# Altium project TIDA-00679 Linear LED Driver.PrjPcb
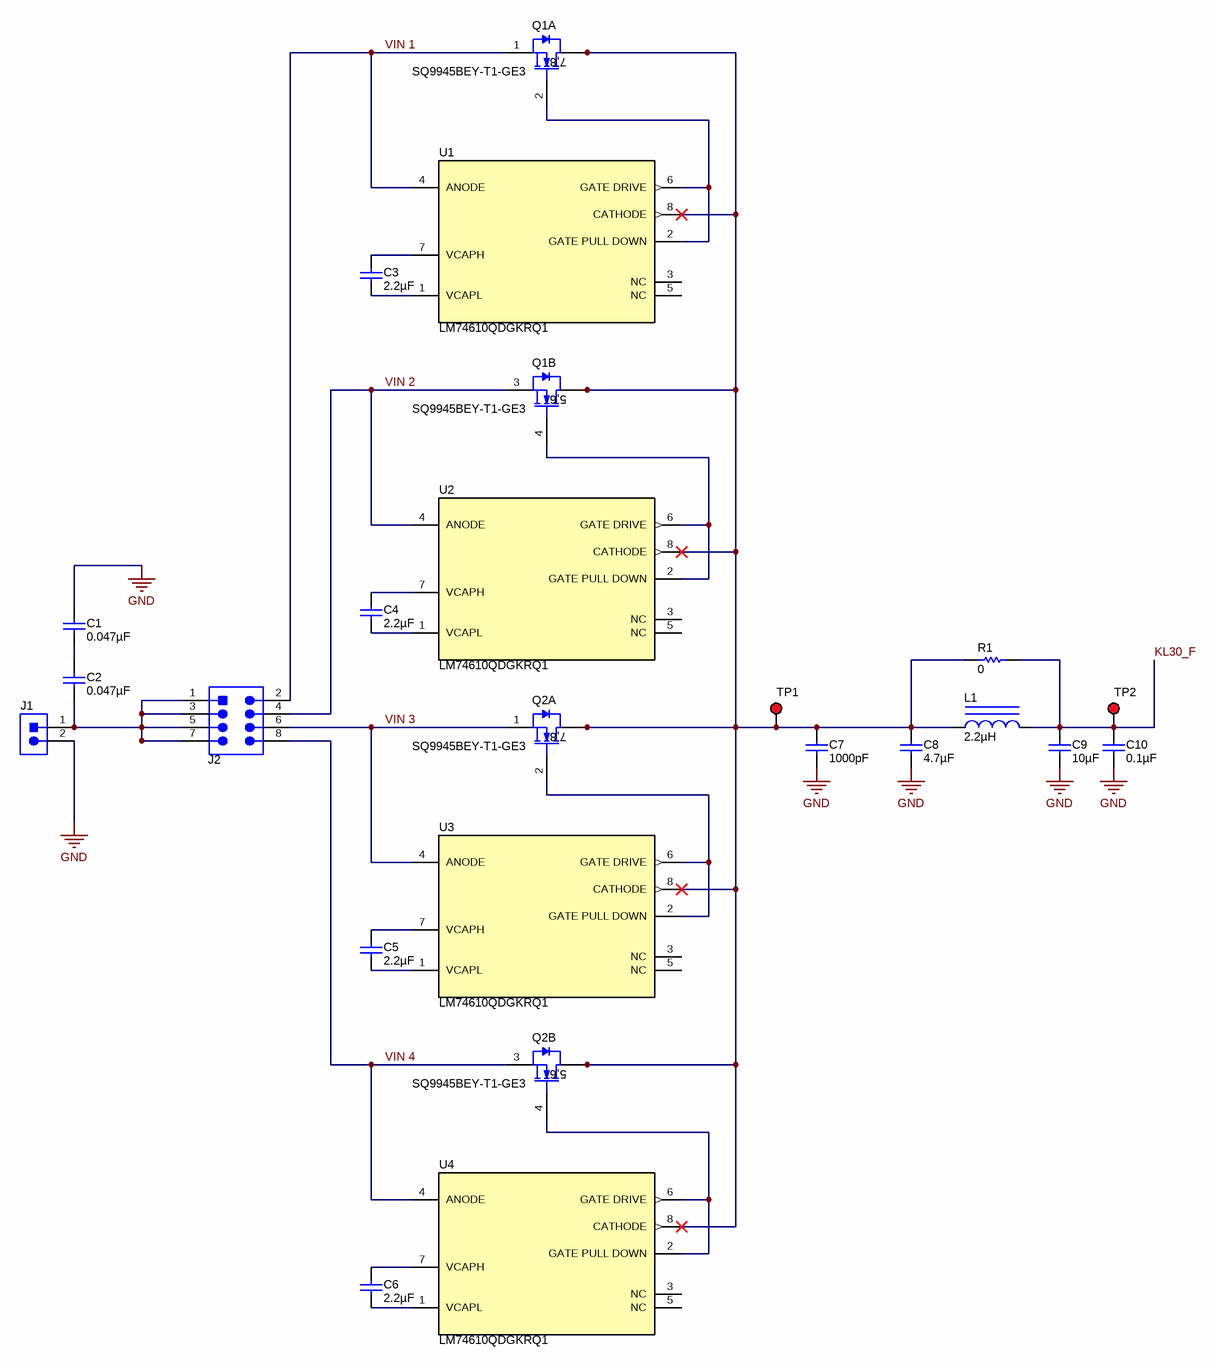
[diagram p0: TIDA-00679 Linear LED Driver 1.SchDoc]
CopyrightYear: 2015; EVM_Orderable: N/A; PCB_Layout: Robert Regensburger; PCB_Rev: E1; PRJ_Customer: Public Release; PRJ_Engineer: Robert Regensburger; PRJ_Number: TIDA-00679; PRJ_Title: Linear LED Driver; SCH_Rev: E1; TechSupport: http://www.ti.com/support; TID: TIDA-00679
3 sheets, 158 parts. Net scope: global (net labels, ports and power ports of the same name join across sheets).
Board file: TIDA-00679 Linear LED Driver.PcbDoc
Sheets:
  TIDA-00679 Linear LED Driver 1.SchDoc
  TIDA-00679 Linear LED Driver 2.SchDoc
  TIDA-00679 Linear LED Driver_Hardware.SchDoc

## Sheet TIDA-00679 Linear LED Driver 1.SchDoc: Linear LED Driver
size 431 x 279 mm; Date: Not shown in title block; ApprovedBy: Not shown in title block; CheckedBy: Not shown in title block; Author: Not shown in title block; CompanyName: Not shown in title block; DrawnBy: Robert Regensburger; Engineer: Not shown in title block; Organization: Not shown in title block; Address1: Not shown in title block; Address2: Not shown in title block; Address3: Not shown in title block; Address4: Not shown in title block; DocumentNumber: 2; Revision: Use project parameter SCH_Rev; SheetNumber: 2; SheetTotal: 4; PageSetup: Record=PageOptions¦CenterHorizontal=True¦CenterVertical=True¦PrintScale=0.62¦XCorrection=1.00¦YCorrection=1.00¦PrintKind=0¦BorderSize=5000000¦LeftOffset=0¦BottomOffset=0¦Orientation=2¦PaperLength=1000¦PaperWidth=1000¦Scale=100¦PaperSource=15¦PrintQuality=600¦MediaType=1¦DitherType=10¦PrintScaleMode=1¦PaperKind=Letter

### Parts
C1  ValueDisplayed: 0.047µF  [0603]  (hidden comment: GRM188R71H473KA61D)
C2  ValueDisplayed: 0.047µF  [0603]  (hidden comment: GRM188R71H473KA61D)
C3  ValueDisplayed: 2.2µF  [0805_HV]  (hidden comment: C2012X5R1H225K125AB)
C4  ValueDisplayed: 2.2µF  [0805_HV]  (hidden comment: C2012X5R1H225K125AB)
C5  ValueDisplayed: 2.2µF  [0805_HV]  (hidden comment: C2012X5R1H225K125AB)
C6  ValueDisplayed: 2.2µF  [0805_HV]  (hidden comment: C2012X5R1H225K125AB)
C7  ValueDisplayed: 1000pF  [0603]  (hidden comment: GRM188R72A102KA01D)
C8  ValueDisplayed: 4.7µF  [1206]  (hidden comment: GRM31CR71H475KA12L)
C9  ValueDisplayed: 10µF  [1210]  (hidden comment: GRM32ER71H106KA12L)
C10  ValueDisplayed: 0.1µF  [0603]  (hidden comment: C1608X7R1H104K080AA)
J1  1725656  [CONN_1725656]  (value not drawn)
J2  PEC04DAAN  [CONN_PEC04DAAN]  (value not drawn)
L1  ValueDisplayed: 2.2µH  [WE-SPC_4838]  (hidden comment: 74408943022)
Q1  SQ9945BEY-T1-GE3  [SOIC-8]  (parts A,B of 2)
Q2  SQ9945BEY-T1-GE3  [SOIC-8]  (parts A,B of 2)
R1  ValueDisplayed: 0  [0603]  (hidden comment: RC0603JR-070RL)
TP1  5000  [Keystone5000]  (value not drawn)
TP2  5000  [Keystone5000]  (value not drawn)
U1  LM74610QDGKRQ1  [DGK0008A_N]
U2  LM74610QDGKRQ1  [DGK0008A_N]
U3  LM74610QDGKRQ1  [DGK0008A_N]
U4  LM74610QDGKRQ1  [DGK0008A_N]

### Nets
GND: C1.1 C7.2 C8.2 C9.2 C10.2 J1.2  [project net REVGND]
KL30_F: C9.1 C10.1 L1.2 R1.2 TP2.1
VIN 1: J2.2 Q1.1(S) U1.4(ANODE)
VIN 2: J2.4 Q1.3(S) U2.4(ANODE)
VIN 3: J2.6 Q2.1(S) U3.4(ANODE)
VIN 4: J2.8 Q2.3(S) U4.4(ANODE)
NetC1_2: C1.2 C2.1
NetC2_2: C2.2 J1.1 J2.1 J2.3 J2.5 J2.7
NetC3_1: C3.1 U1.7(VCAPH)
NetC3_2: C3.2 U1.1(VCAPL)
NetC4_1: C4.1 U2.7(VCAPH)
NetC4_2: C4.2 U2.1(VCAPL)
NetC5_1: C5.1 U3.7(VCAPH)
NetC5_2: C5.2 U3.1(VCAPL)
NetC6_1: C6.1 U4.7(VCAPH)
NetC6_2: C6.2 U4.1(VCAPL)
NetC7_1: C7.1 C8.1 L1.1 Q1.5(D) Q1.6(D) Q1.7(D) Q1.8(D) Q2.5(D) Q2.6(D) Q2.7(D) Q2.8(D) R1.1 TP1.1 U1.8(CATHODE) U2.8(CATHODE) U3.8(CATHODE) U4.8(CATHODE)
NetQ1_2: Q1.2(G) U1.2(GATE_PULL_DOWN) U1.6(GATE_DRIVE)
NetQ1_4: Q1.4(G) U2.2(GATE_PULL_DOWN) U2.6(GATE_DRIVE)
NetQ2_2: Q2.2(G) U3.2(GATE_PULL_DOWN) U3.6(GATE_DRIVE)
NetQ2_4: Q2.4(G) U4.2(GATE_PULL_DOWN) U4.6(GATE_DRIVE)

Not connected (* = marked no-connect by the designer): U1 3(NC) 5(NC); U2 3(NC) 5(NC); U3 3(NC) 5(NC); U4 3(NC) 5(NC)

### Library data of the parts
C1 C2 = GRM188R71H473KA61D: CAP, CERM, 0.047 µF, 50 V, +/- 10%, X7R, 0603; Manufacturer: MuRata; Polarized: N; CompType: Capacitor; Value: 0.047uF; U/M: EA; Cap_F: 0.000000047; Tolerance_%: 10; Value1: Unknown; VDC_V: 50; Value2: 50V; TaMin_C: -55; TaMax_C: 125; AEC Category: Q200
C3-C6 = C2012X5R1H225K125AB: CAP, CERM, 2.2 µF, 50 V, +/- 10%, X5R, 0805; Manufacturer: TDK; Polarized: N; CompType: Capacitor; Value: 2.2uF; U/M: EA; Cap_F: 0.0000022; Tolerance_%: 10; Value1: Unknown; VDC_V: 50; Value2: 50V; TaMin_C: -55; TaMax_C: 85; Cap_Case: 0805; AEC Category: Q200
C7 = GRM188R72A102KA01D: CAP, CERM, 1000 pF, 100 V, +/- 10%, X7R, 0603; Manufacturer: MuRata; Polarized: N; CompType: Capacitor; Value: 1000pF; U/M: EA; Cap_F: 0.000000001; Tolerance_%: 10; Value1: Unknown; VDC_V: 100; Value2: 100V; TaMin_C: -55; TaMax_C: 125; AEC Category: Q200
C8 = GRM31CR71H475KA12L: CAP, CERM, 4.7 µF, 50 V, +/- 10%, X7R, 1206; Manufacturer: MuRata; Polarized: N; CompType: Capacitor; Value: 4.7uF; U/M: EA; Cap_F: 0.0000047; Tolerance_%: 10; Value1: Unknown; VDC_V: 50; Value2: 50V; TaMin_C: -55; TaMax_C: 125; Cap_Case: 2220; AEC Category: Q200
C9 = GRM32ER71H106KA12L: CAP, CERM, 10 µF, 50 V, +/- 10%, X7R, 1210; Manufacturer: MuRata; Polarized: N; CompType: Capacitor; Value: 10uF; U/M: EA; Cap_F: 0.00001; Tolerance_%: 10; Value1: Unknown; VDC_V: 50; Value2: 50V; TaMin_C: -55; TaMax_C: 125; AEC Category: Q200
C10 = C1608X7R1H104K080AA: CAP, CERM, 0.1 µF, 50 V, +/- 10%, X7R, 0603; Manufacturer: TDK; Polarized: N; CompType: Capacitor; Value: 0.1uF; U/M: EA; Cap_F: 0.0000001; Tolerance_%: 10; Value1: Unknown; VDC_V: 50; Value2: 50V; TaMin_C: -55; TaMax_C: 125; AEC Category: Q200
J1 = 1725656: Terminal Block, 100mil, 2x1, 6A, 63V, TH; Manufacturer: Phoenix Contact; SymbolCreator: a0412235
J2 = PEC04DAAN: Header, 100mil, 4x2, Tin, TH; Manufacturer: Sullins Connector Solutions; SymbolCreator: a0411947; Pitch_mm: 2.54; Gender: Male; Shrouded: N; Row_Count: 2; Current_A: 3; Voltage_V: 1800; Cert_UL: Y
L1 = 74408943022: Inductor, Shielded Drum Core, Ferrite, 2.2 µH, 3 A, 0.026 ohm, SMD; Manufacturer: Wurth Elektronik; Value: 2.2uH; Ind_H: 2.2E-6; Imax_A: 3; Irms: 3A @ 40C rise; Isat: 4.6A @ 35% inductance drop; DCR_ohm: 0.026; Value2: 3A; AEC Category: Q200
Q1 Q2 = SQ9945BEY-T1-GE3: MOSFET, N-CH, 60 V, 5.4 A, SOIC-8; Manufacturer: Vishay-Siliconix; Alternate Manufacturer: None; U/M: EA; ChType: N; Value: 60V; VdsMax_V: 60; Value1: 0.082 ohm; Rdson45_ohm: 0.082; Value2: 8 nC; QgTyp_nC: 8; Vgs_V: 20; IdsMax_A: 5.4; AEC Category: Q101
R1 = RC0603JR-070RL: RES, 0, 5%, 0.1 W, 0603; Manufacturer: Yageo America; CompType: Resistor; Value: 0; Value_Code: 0000; Tolerance_%: 5; Power_W: 0.1; Value2: 0.1W; VDC_V: 50; TempCo: 200 ppm/C; EIA_Code: E24; U/M: EA; AEC Category: Q200
TP1 TP2 = 5000: Test Point, Miniature, Red, TH; Manufacturer: Keystone; CompType: Test Point Loop; ContactFinish: Silver
U1-U4 = LM74610QDGKRQ1: Smart Diode Controller, DGK0008A; Manufacturer: Texas Instruments; SymbolCreator: Altium; CompType: IC; U/M: EA

## Sheet TIDA-00679 Linear LED Driver 2.SchDoc: Linear LED Driver
size 431 x 279 mm; Date: Not shown in title block; ApprovedBy: Not shown in title block; CheckedBy: Not shown in title block; Author: Not shown in title block; CompanyName: Not shown in title block; DrawnBy: Robert Regensburger; Engineer: Not shown in title block; Organization: Not shown in title block; Address1: Not shown in title block; Address2: Not shown in title block; Address3: Not shown in title block; Address4: Not shown in title block; DocumentNumber: 3; Revision: Use project parameter SCH_Rev; SheetNumber: 3; SheetTotal: 4; PageSetup: Record=PageOptions¦CenterHorizontal=True¦CenterVertical=True¦PrintScale=0.65¦XCorrection=1.00¦YCorrection=1.00¦PrintKind=0¦BorderSize=5000000¦LeftOffset=0¦BottomOffset=0¦Orientation=2¦PaperLength=2970¦PaperWidth=2100¦Scale=100¦PaperSource=7¦PrintQuality=600¦MediaType=1¦DitherType=10¦PrintScaleMode=1¦PaperKind=A4¦PaperIndex=9
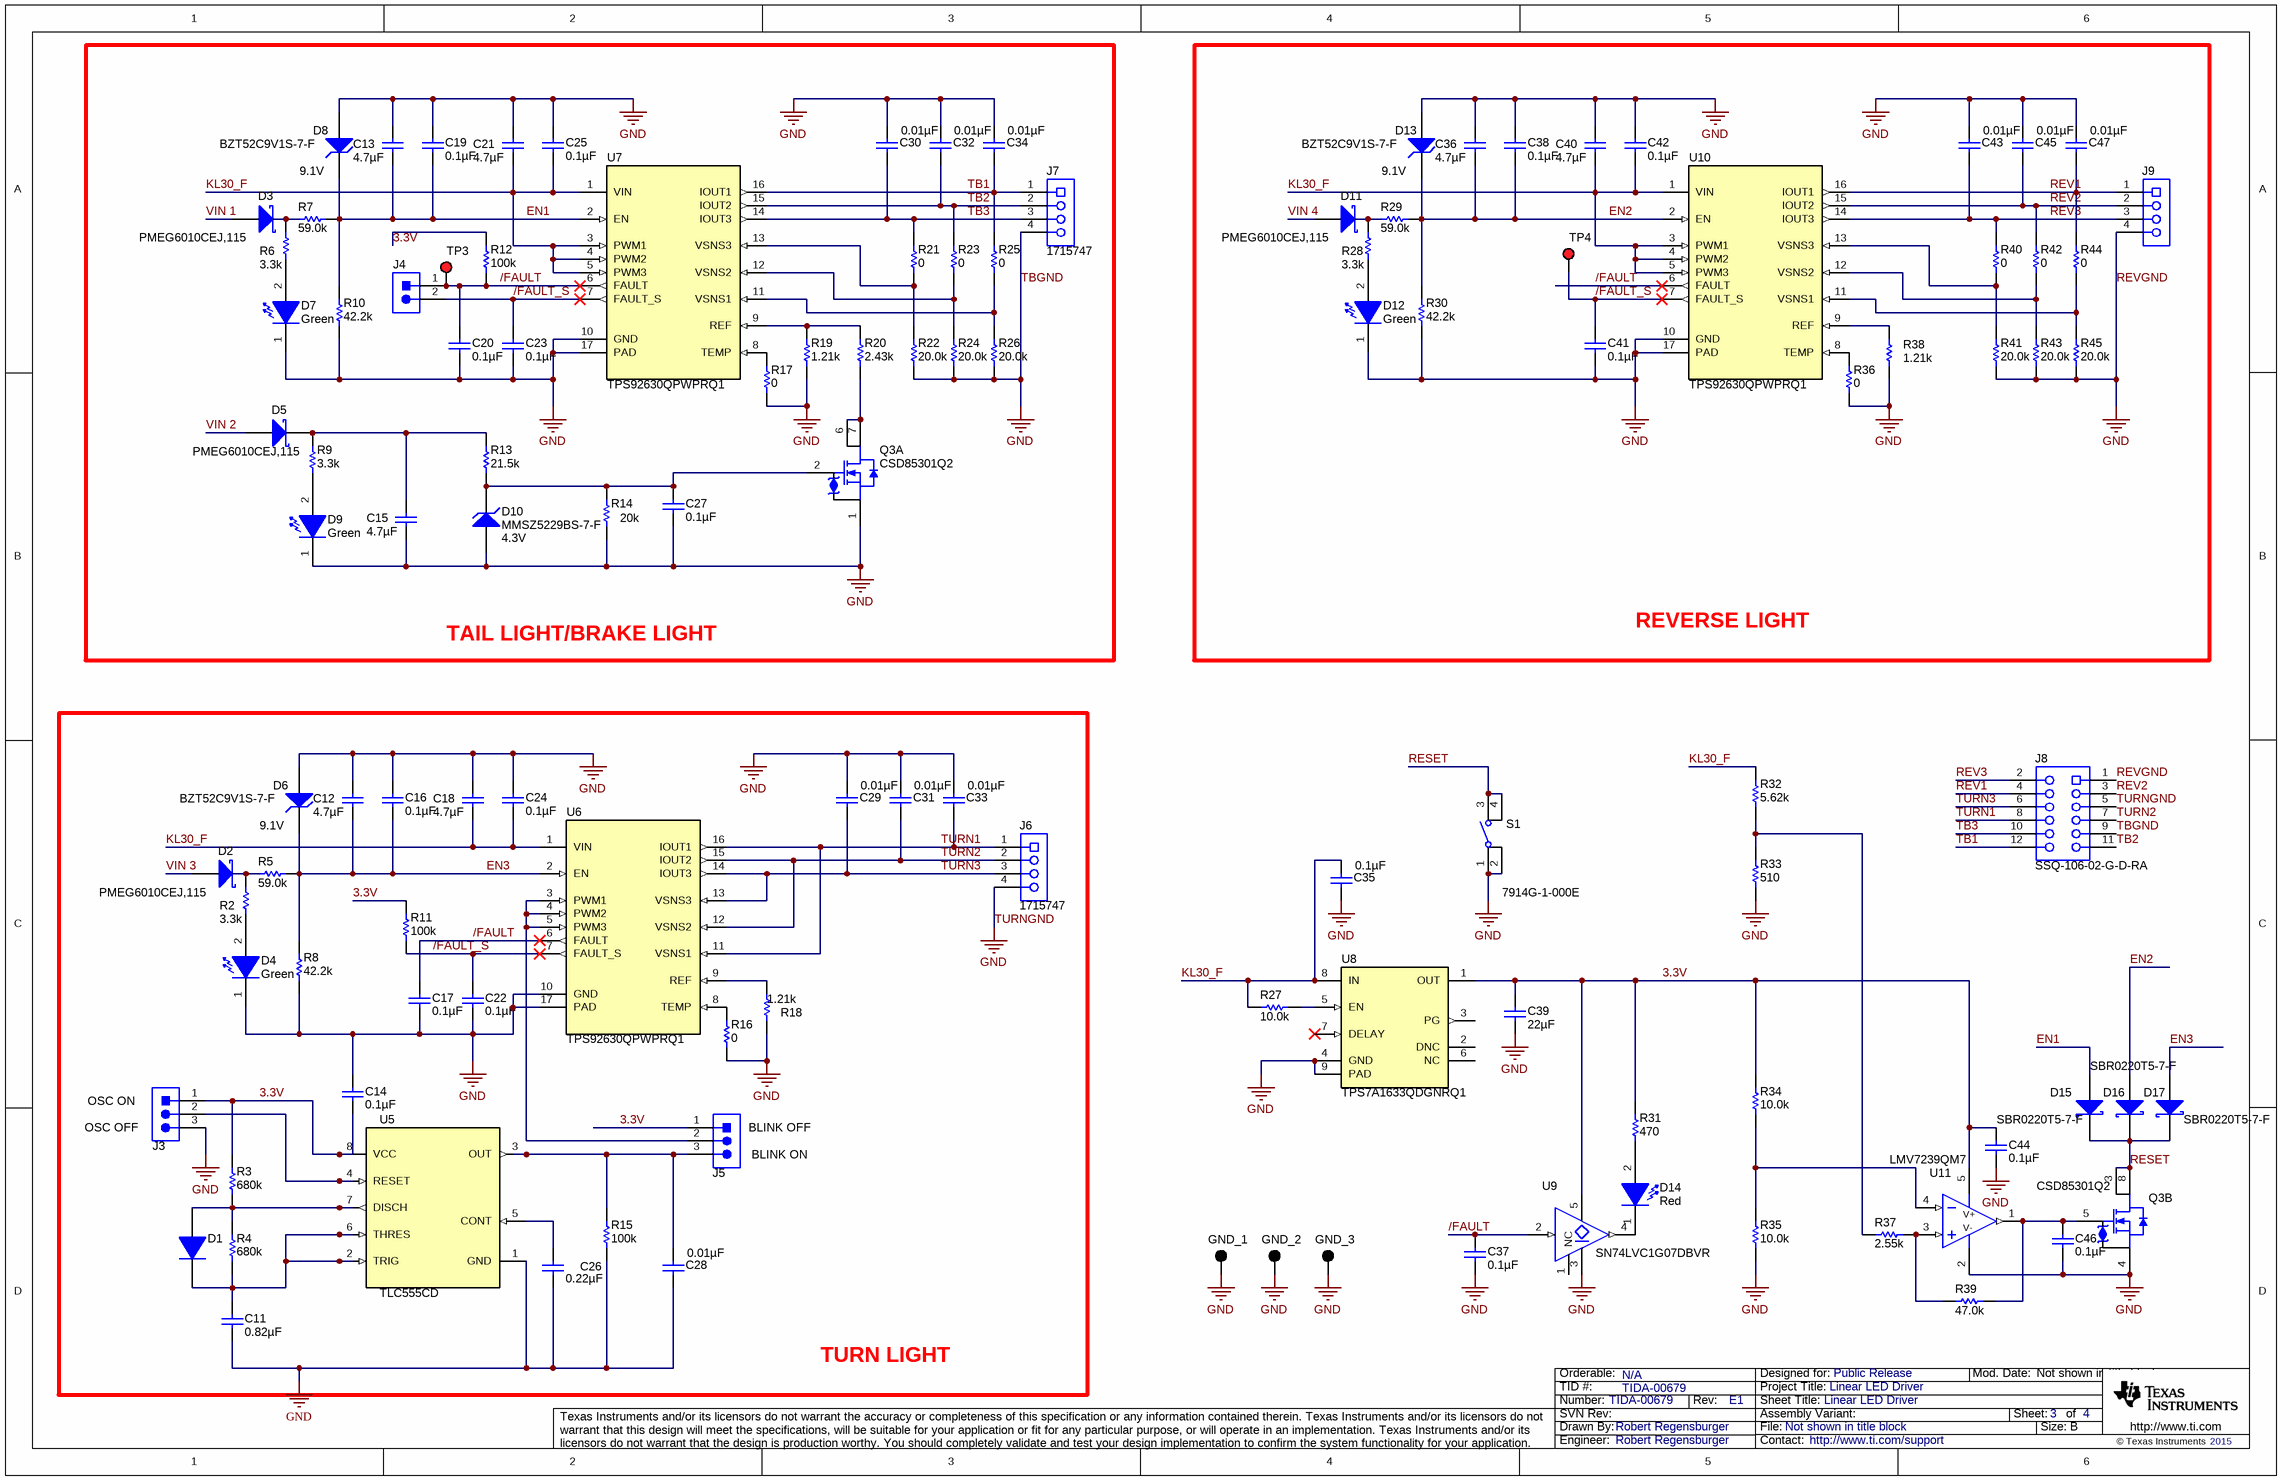
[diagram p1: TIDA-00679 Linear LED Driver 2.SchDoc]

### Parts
C11  ValueDisplayed: 0.82µF  [0805_HV]  (hidden comment: GRM219R71E824KA88D)
C12  ValueDisplayed: 4.7µF  [1206]  (hidden comment: GRM31CR71H475KA12L)
C13  ValueDisplayed: 4.7µF  [1206]  (hidden comment: GRM31CR71H475KA12L)
C14  ValueDisplayed: 0.1µF  [0603]  (hidden comment: 06035C104KAT2A)
C15  ValueDisplayed: 4.7µF  [1206]  (hidden comment: GRM31CR71H475KA12L)
C16  ValueDisplayed: 0.1µF  [0603]  (hidden comment: 06035C104KAT2A)
C17  ValueDisplayed: 0.1µF  [0603]  (hidden comment: 06035C104KAT2A)
C18  ValueDisplayed: 4.7µF  [1206]  (hidden comment: GRM31CR71H475KA12L)
C19  ValueDisplayed: 0.1µF  [0603]  (hidden comment: 06035C104KAT2A)
C20  ValueDisplayed: 0.1µF  [0603]  (hidden comment: 06035C104KAT2A)
C21  ValueDisplayed: 4.7µF  [1206]  (hidden comment: GRM31CR71H475KA12L)
C22  ValueDisplayed: 0.1µF  [0603]  (hidden comment: 06035C104KAT2A)
C23  ValueDisplayed: 0.1µF  [0603]  (hidden comment: 06035C104KAT2A)
C24  ValueDisplayed: 0.1µF  [0603]  (hidden comment: 06035C104KAT2A)
C25  ValueDisplayed: 0.1µF  [0603]  (hidden comment: 06035C104KAT2A)
C26  ValueDisplayed: 0.22µF  [0805_HV]  (hidden comment: 0805YC224JAT2A)
C27  ValueDisplayed: 0.1µF  [0603]  (hidden comment: 06035C104KAT2A)
C28  ValueDisplayed: 0.01µF  [0603]  (hidden comment: 06031C103JAT2A)
C29  ValueDisplayed: 0.01µF  [0603]  (hidden comment: 06031C103JAT2A)
C30  ValueDisplayed: 0.01µF  [0603]  (hidden comment: 06031C103JAT2A)
C31  ValueDisplayed: 0.01µF  [0603]  (hidden comment: 06031C103JAT2A)
C32  ValueDisplayed: 0.01µF  [0603]  (hidden comment: 06031C103JAT2A)
C33  ValueDisplayed: 0.01µF  [0603]  (hidden comment: 06031C103JAT2A)
C34  ValueDisplayed: 0.01µF  [0603]  (hidden comment: 06031C103JAT2A)
C35  ValueDisplayed: 0.1µF  [0603]  (hidden comment: C1608X7R1H104K)
C36  ValueDisplayed: 4.7µF  [1206]  (hidden comment: GRM31CR71H475KA12L)
C37  ValueDisplayed: 0.1µF  [0603]  (hidden comment: 0603YC104JAT2A)
C38  ValueDisplayed: 0.1µF  [0603]  (hidden comment: 06035C104KAT2A)
C39  ValueDisplayed: 22µF  [0603]  (hidden comment: C1608X5R1A226M080AC)
C40  ValueDisplayed: 4.7µF  [1206]  (hidden comment: GRM31CR71H475KA12L)
C41  ValueDisplayed: 0.1µF  [0603]  (hidden comment: 06035C104KAT2A)
C42  ValueDisplayed: 0.1µF  [0603]  (hidden comment: 06035C104KAT2A)
C43  ValueDisplayed: 0.01µF  [0603]  (hidden comment: 06031C103JAT2A)
C44  ValueDisplayed: 0.1µF  [0603]  (hidden comment: 0603YC104JAT2A)
C45  ValueDisplayed: 0.01µF  [0603]  (hidden comment: 06031C103JAT2A)
C46  ValueDisplayed: 0.1µF  [0603]  (hidden comment: 0603YC104JAT2A)
C47  ValueDisplayed: 0.01µF  [0603]  (hidden comment: 06031C103JAT2A)
D1  1N4148W-7-F  [SOD-123]  (value not drawn)
D2  PMEG6010CEJ,115  [SOD-323F]
D3  PMEG6010CEJ,115  [SOD-323F]
D4  value Green  [SML-P1_GREEN]  (hidden comment: SML-P12PTT86)
D5  PMEG6010CEJ,115  [SOD-323F]
D6  BZT52C9V1S-7-F  value 9.1V  [sod-323]
D7  value Green  [SML-P1_GREEN]  (hidden comment: SML-P12PTT86)
D8  BZT52C9V1S-7-F  value 9.1V  [sod-323]
D9  value Green  [SML-P1_GREEN]  (hidden comment: SML-P12PTT86)
D10  MMSZ5229BS-7-F  value 4.3V  [sod-323]
D11  PMEG6010CEJ,115  [SOD-323F]
D12  value Green  [SML-P1_GREEN]  (hidden comment: SML-P12PTT86)
D13  BZT52C9V1S-7-F  value 9.1V  [sod-323]
D14  value Red  [SML-P1_RED]  (hidden comment: SML-P12UTT86)
D15  SBR0220T5-7-F  [SOD-523]
D16  SBR0220T5-7-F  [SOD-523]
D17  SBR0220T5-7-F  [SOD-523]
GND_1  5011  [Keystone5011]  (value not drawn)
GND_2  5011  [Keystone5011]  (value not drawn)
GND_3  5011  [Keystone5011]  (value not drawn)
J3  PEC03SAAN  [CONN_PEC03SAAN]  (value not drawn)
J4  PEC02SAAN  [CONN_PEC02SAAN]  (value not drawn)
J5  PEC03SAAN  [CONN_PEC03SAAN]  (value not drawn)
J6  1715747  [Phoenix_1715747]
J7  1715747  [Phoenix_1715747]
J8  SSQ-106-02-G-D-RA  [SSQ-106-02-G-D-RA]
J9  1715747  [Phoenix_1715747]  (value not drawn)
Q3  CSD85301Q2  [DQK0006B]  (parts A,B of 2)
R2  ValueDisplayed: 3.3k  [0603]  (hidden comment: CRCW06033K30JNEA)
R3  ValueDisplayed: 680k  [0805_HV]  (hidden comment: CRCW0805680KJNEA)
R4  ValueDisplayed: 680k  [0805_HV]  (hidden comment: CRCW0805680KJNEA)
R5  ValueDisplayed: 59.0k  [0603]  (hidden comment: RC0603FR-0759KL)
R6  ValueDisplayed: 3.3k  [0603]  (hidden comment: CRCW06033K30JNEA)
R7  ValueDisplayed: 59.0k  [0603]  (hidden comment: RC0603FR-0759KL)
R8  ValueDisplayed: 42.2k  [0603]  (hidden comment: RC0603FR-0742K2L)
R9  ValueDisplayed: 3.3k  [0603]  (hidden comment: CRCW06033K30JNEA)
R10  ValueDisplayed: 42.2k  [0603]  (hidden comment: RC0603FR-0742K2L)
R11  ValueDisplayed: 100k  [0603]  (hidden comment: CRCW0603100KFKEA)
R12  ValueDisplayed: 100k  [0603]  (hidden comment: CRCW0603100KFKEA)
R13  ValueDisplayed: 21.5k  [0805_HV]  (hidden comment: CRCW080521K5FKEA)
R14  ValueDisplayed: 20k  [0805_HV]  (hidden comment: CRCW080520K0JNEA)
R15  ValueDisplayed: 100k  [0805_HV]  (hidden comment: CRCW0805100KFKEA)
R16  ValueDisplayed: 0  [0603]  (hidden comment: CRCW06030000Z0EA)
R17  ValueDisplayed: 0  [0603]  (hidden comment: CRCW06030000Z0EA)
R18  ValueDisplayed: 1.21k  [0603]  (hidden comment: CRCW06031K21FKEA)
R19  ValueDisplayed: 1.21k  [0603]  (hidden comment: CRCW06031K21FKEA)
R20  ValueDisplayed: 2.43k  [0603]  (hidden comment: CRCW06032K43FKEA)
R21  ValueDisplayed: 0  [0603]  (hidden comment: CRCW06030000Z0EA)
R22  ValueDisplayed: 20.0k  [0603]  (hidden comment: CRCW060320K0FKEA)
R23  ValueDisplayed: 0  [0603]  (hidden comment: CRCW06030000Z0EA)
R24  ValueDisplayed: 20.0k  [0603]  (hidden comment: CRCW060320K0FKEA)
R25  ValueDisplayed: 0  [0603]  (hidden comment: CRCW06030000Z0EA)
R26  ValueDisplayed: 20.0k  [0603]  (hidden comment: CRCW060320K0FKEA)
R27  ValueDisplayed: 10.0k  [0603]  (hidden comment: CRCW060310K0FKEA)
R28  ValueDisplayed: 3.3k  [0603]  (hidden comment: CRCW06033K30JNEA)
R29  ValueDisplayed: 59.0k  [0603]  (hidden comment: RC0603FR-0759KL)
R30  ValueDisplayed: 42.2k  [0603]  (hidden comment: RC0603FR-0742K2L)
R31  ValueDisplayed: 470  [0603]  (hidden comment: RC0603FR-07470RL)
R32  ValueDisplayed: 5.62k  [0603]  (hidden comment: CRCW06035K62FKEA)
R33  ValueDisplayed: 510  [0603]  (hidden comment: RC0603FR-07510RL)
R34  ValueDisplayed: 10.0k  [0603]  (hidden comment: CRCW060310K0FKEA)
R35  ValueDisplayed: 10.0k  [0603]  (hidden comment: CRCW060310K0FKEA)
R36  ValueDisplayed: 0  [0603]  (hidden comment: CRCW06030000Z0EA)
R37  ValueDisplayed: 2.55k  [0603]  (hidden comment: RC0603FR-072K55L)
R38  ValueDisplayed: 1.21k  [0603]  (hidden comment: CRCW06031K21FKEA)
R39  ValueDisplayed: 47.0k  [0603]  (hidden comment: RC0603FR-0747KL)
R40  ValueDisplayed: 0  [0603]  (hidden comment: CRCW06030000Z0EA)
R41  ValueDisplayed: 20.0k  [0603]  (hidden comment: CRCW060320K0FKEA)
R42  ValueDisplayed: 0  [0603]  (hidden comment: CRCW06030000Z0EA)
R43  ValueDisplayed: 20.0k  [0603]  (hidden comment: CRCW060320K0FKEA)
R44  ValueDisplayed: 0  [0603]  (hidden comment: CRCW06030000Z0EA)
R45  ValueDisplayed: 20.0k  [0603]  (hidden comment: CRCW060320K0FKEA)
S1  7914G-1-000E  [SW_7914G-1-000E]
TP3  5000  [Keystone5000]  (value not drawn)
TP4  5000  [Keystone5000]  (value not drawn)
U5  TLC555CD  [D0008A_N]
U6  TPS92630QPWPRQ1  [PWP0016F_N]
U7  TPS92630QPWPRQ1  [PWP0016F_M]
U8  TPS7A1633QDGNRQ1  [DGN0008C_N]
U9  SN74LVC1G07DBVR  [DBV0005A_N]
U10  TPS92630QPWPRQ1  [PWP0016F_M]
U11  LMV7239QM7  [DCK0005A_N]

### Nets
REVGND: C11.2 C12.1 C13.1 C14.1 C15.2 C16.1 C17.2 C18.1 C19.1 C20.2 C21.1 C22.2 C23.2 C24.1 C25.1 C26.2 C27.2 C28.2 C29.1 C30.1 C31.1 C32.1 C33.1 C34.1 C35.2 C36.1 C37.2 C38.1 C39.2 C40.1 C41.2 C42.1 C43.1 C44.1 C45.1 C46.1 C47.1 D4.1(K) D6.2(A) D7.1(K) D8.2(A) D9.1(K) D10.2(A) D12.1(K) D13.2(A) GND_1.1 GND_2.1 GND_3.1 J3.3 J6.4 J7.4 J8.1 J8.5 J8.9 J9.4 Q3.1(S1) Q3.4(S2) R8.1 R10.1 R14.1 R15.1 R16.1 R17.1 R18.1 R19.1 R22.1 R24.1 R26.1 R30.1 R33.1 R35.1 R36.1 R38.1 R41.1 R43.1 R45.1 S1.1 S1.2 U5.1(GND) U6.10(GND) U6.17(PAD) U7.10(GND) U7.17(PAD) U8.4(GND) U8.9(PAD) U9.3(GND) U10.10(GND) U10.17(PAD) U11.2(V-)  [also labelled GND, TBGND, TURNGND]
3.3V: C14.2 C39.1 C44.2 J3.1 J5.1 R3.2 R11.2 R12.2 R31.2 R34.2 U5.8(VCC) U8.1(OUT) U9.5(VCC) U11.5(V+)
/FAULT: C17.1 C20.1 C37.1 J4.1 R12.1 TP3.1 U6.6(FAULT) U7.6(FAULT) U9.2(A) U10.6(FAULT)
/FAULT_S: C22.1 C23.1 C41.1 J4.2 R11.1 TP4.1 U6.7(FAULT_S) U7.7(FAULT_S) U10.7(FAULT_S)
EN1: C13.2 C19.2 D8.1(K) D15.2(A) R7.2 R10.2 U7.2(EN)
EN2: C36.2 C38.2 D13.1(K) D16.2(A) R29.2 R30.2 U10.2(EN)
EN3: C12.2 C16.2 D6.1(K) D17.2(A) R5.2 R8.2 U6.2(EN)
KL30_F: C18.2 C21.2 C24.2 C25.2 C35.1 C40.2 C42.2 R27.2 R32.2 U6.1(VIN) U7.1(VIN) U7.3(PWM1) U7.4(PWM2) U7.5(PWM3) U8.8(IN) U10.1(VIN) U10.3(PWM1) U10.4(PWM2) U10.5(PWM3)
RESET: D15.1(K) D16.1(K) D17.1(K) Q3.3(D2) Q3.8(D2) S1.3 S1.4
REV1: C47.2 J8.4 J9.1 R44.2 U10.16(IOUT1)
REV2: C45.2 J8.3 J9.2 R42.2 U10.15(IOUT2)
REV3: C43.2 J8.2 J9.3 R40.2 U10.14(IOUT3)
TB1: C34.2 J7.1 J8.12 R25.2 U7.16(IOUT1)
TB2: C32.2 J7.2 J8.11 R23.2 U7.15(IOUT2)
TB3: C30.2 J7.3 J8.10 R21.2 U7.14(IOUT3)
TURN1: C33.2 J6.1 J8.8 U6.11(VSNS1) U6.16(IOUT1)
TURN2: C31.2 J6.2 J8.7 U6.12(VSNS2) U6.15(IOUT2)
TURN3: C29.2 J6.3 J8.6 U6.13(VSNS3) U6.14(IOUT3)
VIN 1: D3.2(A)
VIN 2: D5.2(A)
VIN 3: D2.2(A)
VIN 4: D11.2(A)
NetC11_1: C11.1 D1.1(K) R4.1 U5.2(TRIG) U5.6(THRES)
NetC15_1: C15.1 D5.1(K) R9.2 R13.2
NetC26_1: C26.1 U5.5(CONT)
NetC27_1: C27.1 D10.1(K) Q3.2(G1) R13.1 R14.2
NetC28_1: C28.1 J5.3 R15.2 U5.3(OUT)
NetC46_2: C46.2 Q3.5(G2) R39.1 U11.1(OUT)
NetD1_2: D1.2(A) R3.1 R4.2 U5.7(DISCH)
NetD2_1: D2.1(K) R2.2 R5.1
NetD3_1: D3.1(K) R6.2 R7.1
NetD4_2: D4.2(A) R2.1
NetD7_2: D7.2(A) R6.1
NetD9_2: D9.2(A) R9.1
NetD11_1: D11.1(K) R28.2 R29.1
NetD12_2: D12.2(A) R28.1
NetD14_1: D14.1(K) U9.4(Y)
NetD14_2: D14.2(A) R31.1
NetJ3_2: J3.2 U5.4(RESET)
NetJ5_2: J5.2 U6.3(PWM1) U6.4(PWM2) U6.5(PWM3)
NetQ3_6: Q3.6(D1) Q3.7(D1) R20.1
NetR16_2: R16.2 U6.8(TEMP)
NetR17_2: R17.2 U7.8(TEMP)
NetR18_2: R18.2 U6.9(REF)
NetR19_2: R19.2 R20.2 U7.9(REF)
NetR21_1: R21.1 R22.2 U7.13(VSNS3)
NetR23_1: R23.1 R24.2 U7.12(VSNS2)
NetR25_1: R25.1 R26.2 U7.11(VSNS1)
NetR27_1: R27.1 U8.5(EN)
NetR32_1: R32.1 R33.2 R37.1
NetR34_1: R34.1 R35.2 U11.4(IN-)
NetR36_2: R36.2 U10.8(TEMP)
NetR37_2: R37.2 R39.2 U11.3(IN+)
NetR38_2: R38.2 U10.9(REF)
NetR40_1: R40.1 R41.2 U10.13(VSNS3)
NetR42_1: R42.1 R43.2 U10.12(VSNS2)
NetR44_1: R44.1 R45.2 U10.11(VSNS1)

Not connected (* = marked no-connect by the designer): U8 2(DNC) 3(PG) 6(NC) 7(DELAY)*; U9 1(NC)

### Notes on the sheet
- TAIL LIGHT/BRAKE LIGHT
- REVERSE LIGHT
- (near J3) OSC ON
- (near J3) OSC OFF
- (near J5) BLINK ON
- (near J5) BLINK OFF
- TURN LIGHT

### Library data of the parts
C11 = GRM219R71E824KA88D: CAP, CERM, 0.82 µF, 25 V, +/- 10%, X7R, 0805; Manufacturer: MuRata; Polarized: N; CompType: Capacitor; Value: 0.82uF; U/M: EA; Cap_F: 0.00000082; Tolerance_%: 10; Value1: Unknown; VDC_V: 25; Value2: 25V; TaMin_C: -55; TaMax_C: 125; Cap_Case: 0805; AEC Category: Q200
C12 C13 C15 C18 C21 C36 C40 = GRM31CR71H475KA12L: as C8 on sheet TIDA-00679 Linear LED Driver 1
C14 C16 C17 C19 C20 C22-C25 C27 C38 C41 C42 = 06035C104KAT2A: CAP, CERM, 0.1 µF, 50 V, +/- 10%, X7R, 0603; Manufacturer: AVX; Polarized: N; CompType: Capacitor; Value: 0.1uF; U/M: EA; Cap_F: 0.0000001; Tolerance_%: 10; Value1: Unknown; VDC_V: 50; Value2: 50V; TaMin_C: -55; TaMax_C: 125; AEC Category: Q200
C26 = 0805YC224JAT2A: CAP, CERM, 0.22 µF, 16 V, +/- 5%, X7R, 0805; Manufacturer: AVX; Polarized: N; CompType: Capacitor; Value: 0.22uF; U/M: EA; Cap_F: 0.00000022; Tolerance_%: 5; ESR_ohm: 0.016; Value1: 0.016 ohm; VDC_V: 16; Value2: 16V; TaMin_C: -55; TaMax_C: 125; Cap_Case: 0805; AEC Category: Q200
C28-C34 C43 C45 C47 = 06031C103JAT2A: CAP, CERM, 0.01 µF, 100 V, +/- 5%, X7R, 0603; Manufacturer: AVX; Polarized: N; CompType: Capacitor; Value: 0.01uF; U/M: EA; Cap_F: 0.00000001; Tolerance_%: 5; ESR_ohm: 0.098; Value1: 0.098 ohm; VDC_V: 100; Value2: 100V; TaMin_C: -55; TaMax_C: 125; AEC Category: Q200
C35 = C1608X7R1H104K: CAP, CERM, 0.1 µF, 50 V, +/- 10%, X7R, 0603; Manufacturer: TDK; Polarized: N; CompType: Capacitor; Value: 0.1uF; U/M: EA; Cap_F: 0.0000001; Tolerance_%: 10; ESR_ohm: 0.017; Value1: 0.017 ohm; VDC_V: 50; Value2: 50V; TaMin_C: -55; TaMax_C: 125; AEC Category: Q200
C37 C44 C46 = 0603YC104JAT2A: CAP, CERM, 0.1 µF, 16 V, +/- 5%, X7R, 0603; Manufacturer: AVX; Polarized: N; CompType: Capacitor; Value: 0.1uF; U/M: EA; Cap_F: 0.0000001; Tolerance_%: 5; ESR_ohm: 0.039; Value1: 0.039 ohm; VDC_V: 16; Value2: 16V; TaMin_C: -55; TaMax_C: 125; AEC Category: Q200
C39 = C1608X5R1A226M080AC: CAP, CERM, 22 µF, 10 V, +/- 20%, X5R, 0603; Manufacturer: TDK; Polarized: N; CompType: Capacitor; Value: 22uF; U/M: EA; Cap_F: 0.000022; Tolerance_%: 20; Value1: Unknown; VDC_V: 10; Value2: 10V; TaMin_C: -55; TaMax_C: 85; AEC Category: Q200
D1 = 1N4148W-7-F: Diode, Ultrafast, 100 V, 0.15 A, SOD-123; Manufacturer: Diodes Inc.; U/M: EA; Vf_V: 1.25; Value: 100V; Value1: 0.15A; Value2: 1.25V; Io_A: 0.15; Vr_V: 100; TJmax_C: 150; AEC Category: Q101
D2 D3 D5 D11 = PMEG6010CEJ,115: Diode, Schottky, 60 V, 1 A, SOD-323F; Manufacturer: NXP Semiconductor; U/M: EA; Vf_V: 0.66; Value: 60V; Value1: 1A; Value2: 0.66V; Io_A: 1; Vr_V: 60; TJmax_C: 150; AEC Category: Q101
D4 D7 D9 D12 = SML-P12PTT86: LED, Green, SMD; Manufacturer: Rohm; Type: AlInGaP; Vf_V: 2.2; Value2: 2.2V; Io_A: 0.02; Value1: W; U/M: EA
D6 D8 D13 = BZT52C9V1S-7-F: Diode, Zener, 9.1 V, 200 mW, SOD-323; Manufacturer: Diodes Inc.; SymbolCreator: a0412235; U/M: EA; Power_W: 0.2; Vz_V: 9.1; Value1: 0.2W; RJA_CperW: 625; AEC Category: Q101
D10 = MMSZ5229BS-7-F: Diode, Zener, 4.3 V, 200 mW, SOD-323; Manufacturer: Diodes Inc.; SymbolCreator: a0412235; U/M: EA; Power_W: 0.2; Vz_V: 4.3; Value1: 0.2W; RJA_CperW: 350; AEC Category: Q101
D14 = SML-P12UTT86: LED, Red, SMD; Manufacturer: Rohm; Type: AlInGaP; Vf_V: 2; Value2: 2V; Io_A: 0.02; Value1: W; U/M: EA
D15-D17 = SBR0220T5-7-F: Diode, Schottky, 20 V, 0.2 A, SOD-523; Manufacturer: Diodes Inc.; U/M: EA; Vf_V: 0.47; Value: 20V; Value1: 0.2A; Value2: 0.47V; Io_A: 0.2; Vr_V: 20; AEC Category: Q101
GND_1-GND_3 = 5011: Test Point, Multipurpose, Black, TH; Manufacturer: Keystone; CompType: Test Point Loop; ContactFinish: Silver
J3 J5 = PEC03SAAN: Header, 100mil, 3x1, Tin, TH; Manufacturer: Sullins Connector Solutions; SymbolCreator: a0799628; Pitch_mm: 2.54; Gender: Male; Shrouded: N; Row_Count: 1; Current_A: 3; Voltage_V: 1800; Cert_UL: Y
J4 = PEC02SAAN: Header, 100mil, 2x1, Tin, TH; Manufacturer: Sullins Connector Solutions; SymbolCreator: a0412235; Pitch_mm: 2.54; Gender: Male; Shrouded: N; Row_Count: 1; Current_A: 3; Voltage_V: 1800; Cert_UL: Y
J6 J7 J9 = 1715747: Terminal Block, 5.08mm, 4x1, TH; Manufacturer: Phoenix Contact; SymbolCreator: a0411947
J8 = SSQ-106-02-G-D-RA: Receptacle, 100mil, 6x2, Gold, R/A, TH; Manufacturer: Samtec; SymbolCreator: a0412235
Q3 = CSD85301Q2: MOSFET, N-CH, 20 V, 6.7 A, DQK0006B; Manufacturer: Texas Instruments; Alternate Manufacturer: None; SymbolCreator: a0411947; U/M: EA; ChType: N; Value: 20V; VdsMax_V: 20; Value1: 0.023 ohm; Rdson45_ohm: 0.023; Value2: 4.2 nC; QgTyp_nC: 4.2; Vgs_V: 10; IdsMax_A: 6.7; AEC Category: Q101
R2 R6 R9 R28 = CRCW06033K30JNEA: RES, 3.3 k, 5%, 0.1 W, 0603; Manufacturer: Vishay-Dale; CompType: Resistor; Value: 3.3k; Res_ohm: 3300; Value_Code: 3k30; Tolerance_%: 5; Power_W: 0.1; Value2: 0.1W; VDC_V: 75; TempCo: 200 ppm/C; EIA_Code: E24; U/M: EA; AEC Category: Q200
R3 R4 = CRCW0805680KJNEA: RES, 680 k, 5%, 0.125 W, 0805; Manufacturer: Vishay-Dale; CompType: Resistor; Value: 680k; Res_ohm: 680000; Tolerance_%: 5; Power_W: 0.125; Value2: 0.125W; VDC_V: 150; TempCo: 200 ppm/C; EIA_Code: E24; U/M: EA; AEC Category: Q200
R5 R7 R29 = RC0603FR-0759KL: RES, 59.0 k, 1%, 0.1 W, 0603; Manufacturer: Yageo America; CompType: Resistor; Value: 59.0k; Res_ohm: 59000; Value_Code: 59k0; Tolerance_%: 1; Power_W: 0.1; Value2: 0.1W; VDC_V: 150; TempCo: 200 ppm/C; EIA_Code: E96; U/M: EA; AEC Category: Q200
R8 R10 R30 = RC0603FR-0742K2L: RES, 42.2 k, 1%, 0.1 W, 0603; Manufacturer: Yageo America; CompType: Resistor; Value: 42.2k; Res_ohm: 42200; Value_Code: 42k2; Tolerance_%: 1; Power_W: 0.1; Value2: 0.1W; VDC_V: 150; TempCo: 200 ppm/C; EIA_Code: E96; U/M: EA; AEC Category: Q200
R11 R12 = CRCW0603100KFKEA: RES, 100 k, 1%, 0.1 W, 0603; Manufacturer: Vishay-Dale; CompType: Resistor; Value: 100k; Res_ohm: 100000; Tolerance_%: 1; Power_W: 0.1; Value2: 0.1W; VDC_V: 75; TempCo: 100 ppm/C; EIA_Code: E96; U/M: EA; AEC Category: Q200
R13 = CRCW080521K5FKEA: RES, 21.5 k, 1%, 0.125 W, 0805; Manufacturer: Vishay-Dale; CompType: Resistor; Value: 21.5k; Res_ohm: 21500; Value_Code: 21k5; Tolerance_%: 1; Power_W: 0.125; Value2: 0.125W; VDC_V: 150; TempCo: 100 ppm/C; EIA_Code: E96; U/M: EA; AEC Category: Q200
R14 = CRCW080520K0JNEA: RES, 20 k, 5%, 0.125 W, 0805; Manufacturer: Vishay-Dale; CompType: Resistor; Value: 20k; Res_ohm: 20000; Value_Code: 20k0; Tolerance_%: 5; Power_W: 0.125; Value2: 0.125W; VDC_V: 150; TempCo: 200 ppm/C; EIA_Code: E24; U/M: EA; AEC Category: Q200
R15 = CRCW0805100KFKEA: RES, 100 k, 1%, 0.125 W, 0805; Manufacturer: Vishay-Dale; CompType: Resistor; Value: 100k; Res_ohm: 100000; Tolerance_%: 1; Power_W: 0.125; Value2: 0.125W; VDC_V: 150; TempCo: 100 ppm/C; EIA_Code: E96; U/M: EA; AEC Category: Q200
R16 R17 R21 R23 R25 R36 R40 R42 R44 = CRCW06030000Z0EA: RES, 0, 5%, 0.1 W, 0603; Manufacturer: Vishay-Dale; CompType: Resistor; Value: 0; Value_Code: 0000; Tolerance_%: 5; Power_W: 0.1; Value2: 0.1W; VDC_V: 75; TempCo: 200 ppm/C; EIA_Code: E24; U/M: EA; AEC Category: Q200
R18 R19 R38 = CRCW06031K21FKEA: RES, 1.21 k, 1%, 0.1 W, 0603; Manufacturer: Vishay-Dale; CompType: Resistor; Value: 1.21k; Res_ohm: 1210; Value_Code: 1k21; Tolerance_%: 1; Power_W: 0.1; Value2: 0.1W; VDC_V: 75; TempCo: 100 ppm/C; EIA_Code: E96; U/M: EA; AEC Category: Q200
R20 = CRCW06032K43FKEA: RES, 2.43 k, 1%, 0.1 W, 0603; Manufacturer: Vishay-Dale; CompType: Resistor; Value: 2.43k; Res_ohm: 2430; Value_Code: 2k43; Tolerance_%: 1; Power_W: 0.1; Value2: 0.1W; VDC_V: 75; TempCo: 100 ppm/C; EIA_Code: E96; U/M: EA; AEC Category: Q200
R22 R24 R26 R41 R43 R45 = CRCW060320K0FKEA: RES, 20.0 k, 1%, 0.1 W, 0603; Manufacturer: Vishay-Dale; CompType: Resistor; Value: 20.0k; Res_ohm: 20000; Value_Code: 20k0; Tolerance_%: 1; Power_W: 0.1; Value2: 0.1W; VDC_V: 75; TempCo: 100 ppm/C; EIA_Code: E96; U/M: EA; AEC Category: Q200
R27 R34 R35 = CRCW060310K0FKEA: RES, 10.0 k, 1%, 0.1 W, 0603; Manufacturer: Vishay-Dale; CompType: Resistor; Value: 10.0k; Res_ohm: 10000; Value_Code: 10k0; Tolerance_%: 1; Power_W: 0.1; Value2: 0.1W; VDC_V: 75; TempCo: 100 ppm/C; EIA_Code: E96; U/M: EA; AEC Category: Q200
R31 = RC0603FR-07470RL: RES, 470, 1%, 0.1 W, 0603; Manufacturer: Yageo America; CompType: Resistor; Value: 470; Value_Code: 470R; Tolerance_%: 1; Power_W: 0.1; Value2: 0.1W; VDC_V: 150; TempCo: 200 ppm/C; U/M: EA; AEC Category: Q200
R32 = CRCW06035K62FKEA: RES, 5.62 k, 1%, 0.1 W, 0603; Manufacturer: Vishay-Dale; CompType: Resistor; Value: 5.62k; Res_ohm: 5620; Value_Code: 5k62; Tolerance_%: 1; Power_W: 0.1; Value2: 0.1W; VDC_V: 75; TempCo: 100 ppm/C; EIA_Code: E96; U/M: EA; AEC Category: Q200
R33 = RC0603FR-07510RL: RES, 510, 1%, 0.1 W, 0603; Manufacturer: Yageo America; CompType: Resistor; Value: 510; Value_Code: 510R; Tolerance_%: 1; Power_W: 0.1; Value2: 0.1W; VDC_V: 150; TempCo: 200 ppm/C; U/M: EA; AEC Category: Q200
R37 = RC0603FR-072K55L: RES, 2.55 k, 1%, 0.1 W, 0603; Manufacturer: Yageo America; CompType: Resistor; Value: 2.55k; Res_ohm: 2550; Value_Code: 2k55; Tolerance_%: 1; Power_W: 0.1; Value2: 0.1W; VDC_V: 150; TempCo: 200 ppm/C; EIA_Code: E96; U/M: EA; AEC Category: Q200
R39 = RC0603FR-0747KL: RES, 47.0 k, 1%, 0.1 W, 0603; Manufacturer: Yageo America; CompType: Resistor; Value: 47.0k; Res_ohm: 47000; Value_Code: 47k0; Tolerance_%: 1; Power_W: 0.1; Value2: 0.1W; VDC_V: 150; TempCo: 200 ppm/C; U/M: EA; AEC Category: Q200
S1 = 7914G-1-000E: Switch, Tactile, SPST-NO, 0.1A, 16V, SMT; Manufacturer: Bourns; SymbolCreator: a0412235; VDC_V: 16; SwitchFunction: Off-Mom; PositionCount: 1; CurrentRating_mA: 100
TP3 TP4 = 5000: as TP1 on sheet TIDA-00679 Linear LED Driver 1
U5 = TLC555CD: LinCMOS Timer, D0008A; Manufacturer: Texas Instruments; SymbolCreator: a0799628; CompType: IC; U/M: EA
U6 U7 U10 = TPS92630QPWPRQ1: Three-Channel Linear LED Driver with Analog and PWM Dimming, PWP0016F; Manufacturer: Texas Instruments; SymbolCreator: a0411947; CompType: IC; U/M: EA
U8 = TPS7A1633QDGNRQ1: 60-V, 5-μA IQ, 100-mA, Low-Dropout VOLTAGE REGULATOR With Enable and Power-Good, DGN0008C; Manufacturer: Texas Instruments; SymbolCreator: a0411947; CompType: IC; U/M: EA
U9 = SN74LVC1G07DBVR: SINGLE BUFFER/DRIVER WITH OPEN-DRAIN OUTPUT, DBV0005A; Alternate PartNumber: SN74LVC1G07DBVT; Manufacturer: Texas Instruments; SymbolCreator: a0411947; CompType: IC; U/M: EA
U11 = LMV7239QM7: Automotive 75 nsec, 2.7V to 5V comparator with Rail-to-Rail Input and Output, DCK0005A; Manufacturer: Texas Instruments; CompType: OpAmp IC

## Sheet TIDA-00679 Linear LED Driver_Hardware.SchDoc: Linear LED Driver
size 431 x 279 mm; Date: Not shown in title block; ApprovedBy: Not shown in title block; CheckedBy: Not shown in title block; Author: Not shown in title block; CompanyName: Not shown in title block; DrawnBy: Robert Regensburger; Engineer: Not shown in title block; Organization: Not shown in title block; Address1: Not shown in title block; Address2: Not shown in title block; Address3: Not shown in title block; Address4: Not shown in title block; DocumentNumber: 4; Revision: Use project parameter SCH_Rev; SheetNumber: 4; SheetTotal: 4; PageSetup: Record=PageOptions¦CenterHorizontal=True¦CenterVertical=True¦PrintScale=1.00¦XCorrection=1.00¦YCorrection=1.00¦PrintKind=0¦BorderSize=5000000¦LeftOffset=0¦BottomOffset=0¦Orientation=2¦PaperLength=1000¦PaperWidth=1000¦Scale=100¦PaperSource=15¦PrintQuality=600¦MediaType=1¦DitherType=10¦PaperKind=Letter¦PrintScaleMode=1
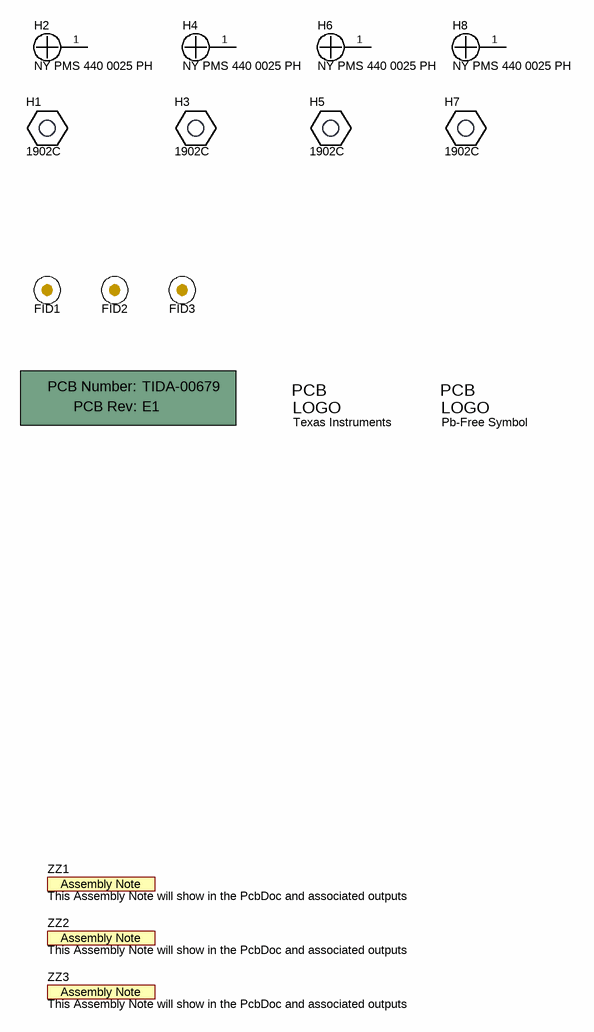
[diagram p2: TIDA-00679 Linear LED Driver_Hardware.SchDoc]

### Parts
!PCB1  Printed Circuit Board  (value not drawn)  (mechanical)
FID1  Fiducial  [Fiducial10-20]  (value not drawn)
FID2  Fiducial  [Fiducial10-20]  (value not drawn)
FID3  Fiducial  [Fiducial10-20]  (value not drawn)
H1  1902C  [Keystone_1902C]
H2  NY PMS 440 0025 PH  [NY PMS 440 0025 PH]
H3  1902C  [Keystone_1902C]
H4  NY PMS 440 0025 PH  [NY PMS 440 0025 PH]
H5  1902C  [Keystone_1902C]
H6  NY PMS 440 0025 PH  [NY PMS 440 0025 PH]
H7  1902C  [Keystone_1902C]
H8  NY PMS 440 0025 PH  [NY PMS 440 0025 PH]
Logo1  Texas Instruments  [TI_Stacked_Overlay_Medium]  (no BOM)
Logo2  Pb-Free Symbol  [Pb-Free_Overlay_Small]  (no BOM)
ZZ1  This Assembly Note will show in the PcbDoc and associated outputs  [AssemblyNote]  (no BOM)
ZZ2  This Assembly Note will show in the PcbDoc and associated outputs  [AssemblyNote]  (no BOM)
ZZ3  This Assembly Note will show in the PcbDoc and associated outputs  [AssemblyNote]  (no BOM)

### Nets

Not connected (* = marked no-connect by the designer): H2 1; H4 1; H6 1; H8 1

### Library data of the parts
!PCB1 = PCB: Manufacturer: Any; PartNumber: TIDA-00679; SymbolCreator: a0412235
FID1-FID3 = Fiducial: Fiducial mark.  There is nothing to buy or mount.; SymbolCreator: codlsc
H1 H3 H5 H7 = 1902C: Standoff, Hex, 0.5"L #4-40 Nylon; Manufacturer: Keystone; CompType: Hardware; SymbolCreator: a0412235
H2 H4 H6 H8 = NY PMS 440 0025 PH: Machine Screw, Round, #4-40 x 1/4, Nylon, Philips panhead; Manufacturer: B&F Fastener Supply; CompType: Hardware; SymbolCreator: codlsc; U/M: EA
Logo1 = TI_Logo: Texas Instrument Corporate Signature; SymbolCreator: a0412235
Logo2 = Pb-Free: SymbolCreator: a0412235
ZZ1-ZZ3 = AssemblyNote: SymbolCreator: codlsc

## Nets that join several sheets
REVGND: TIDA-00679 Linear LED Driver 1 (6 pins), TIDA-00679 Linear LED Driver 2 (89 pins)
KL30_F: TIDA-00679 Linear LED Driver 1 (5 pins), TIDA-00679 Linear LED Driver 2 (19 pins)
VIN 1: TIDA-00679 Linear LED Driver 1 (J2.2 Q1.1 U1.4), TIDA-00679 Linear LED Driver 2 (D3.2)
VIN 2: TIDA-00679 Linear LED Driver 1 (J2.4 Q1.3 U2.4), TIDA-00679 Linear LED Driver 2 (D5.2)
VIN 3: TIDA-00679 Linear LED Driver 1 (J2.6 Q2.1 U3.4), TIDA-00679 Linear LED Driver 2 (D2.2)
VIN 4: TIDA-00679 Linear LED Driver 1 (J2.8 Q2.3 U4.4), TIDA-00679 Linear LED Driver 2 (D11.2)

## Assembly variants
001: not fitted FID1 FID2 FID3 L1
